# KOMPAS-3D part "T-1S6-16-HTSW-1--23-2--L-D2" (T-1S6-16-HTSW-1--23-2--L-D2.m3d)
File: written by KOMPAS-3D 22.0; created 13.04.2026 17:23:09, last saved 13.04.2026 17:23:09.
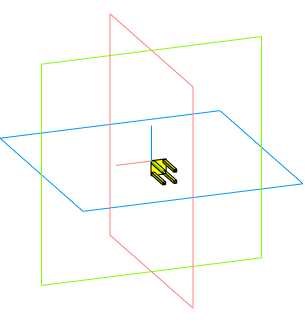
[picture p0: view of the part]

Document properties: Автор: Andrey; Полное имя файла: C:\Users\User1\Documents\T-1S6-16-HTSW-1--23-2--L-D2.m3d

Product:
- Part/product: T-1S6-16-HTSW-1--23-2--L-D2
    Комментарий: T-1S6-16-HTSW-1--23-2--L-D2

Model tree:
1. Операция без истории:1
